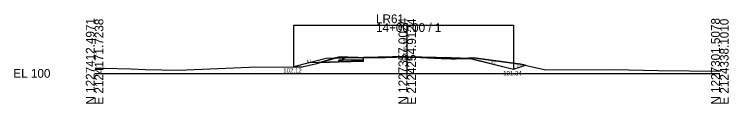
# Model space of a CAD drawing. Extents: x 2121193 to 2127979, y 1225108 to 1234639.
# Drawn here: x 2127750.9 to 2127979.4, y 1229107.5 to 1229136.1 of the extents above; entities that cross this region are included whole.
import ezdxf

# ---------------------------------------------------------------- set-up
doc = ezdxf.new("R2010")
doc.units = 0
for name, color, linetype in [('XS_CELL', 7, 'Continuous'), ('XS_M_DITCH', 7, 'Continuous'), ('XS_M_SHAPES_EARTHWORK', 7, 'Continuous'), ('XS_P_FINISHED_GRADE', 7, 'Continuous'), ('XS_P_FINISHED_GRADE_ELEV_TX', 7, 'Continuous'), ('XS_P_SUBGRADE_GRANULAR', 7, 'Continuous'), ('XS_P_SUBGRADE_LEVELING', 7, 'Continuous'), ('XS_P_SUBGRADE_PAVEMENT', 7, 'Continuous'), ('XS_P_TX_DCH', 7, 'Continuous'), ('XS_P_TX_FS_BS', 7, 'Continuous'), ('XS_X_GROUND', 7, 'Continuous'), ('XS_X_GROUND_TX', 7, 'Continuous')]:
    doc.layers.add(name, color=color, linetype=linetype)

msp = doc.modelspace()

# ---------------------------------------------------------------- linework, layer by layer
at = {"layer": 'XS_CELL'}
for p, q in [((2127876.61, 1229117.21), (2127876.61, 1229133.25)), ((2127776.61, 1229117.21), (2127876.61, 1229117.21)), ((2127876.61, 1229117.21), (2127976.61, 1229117.21))]:
    msp.add_line(p, q, dxfattribs=at)
at = {"layer": 'XS_M_DITCH'}
for p, q in [((2127840.32, 1229119.33), (2127840.32, 1229132.57)), ((2127840.32, 1229132.57), (2127910.61, 1229132.57)), ((2127910.61, 1229132.57), (2127910.61, 1229118.55))]:
    msp.add_line(p, q, dxfattribs=at)
at = {"layer": 'XS_M_SHAPES_EARTHWORK'}
for p, q in [((2127853.28, 1229122.03), (2127848.77, 1229120.69)), ((2127855.01, 1229122.55), (2127853.28, 1229122.03)), ((2127856.72, 1229122.17), (2127853.28, 1229122.03)), ((2127853.28, 1229122.03), (2127856.72, 1229122.17)), ((2127857.65, 1229122.41), (2127855.01, 1229122.55)), ((2127855.89, 1229121.45), (2127856.04, 1229121.7)), ((2127856.04, 1229121.7), (2127855.89, 1229121.45)), ((2127862.61, 1229121.58), (2127855.89, 1229121.45)), ((2127855.89, 1229121.45), (2127862.61, 1229121.58)), ((2127856.04, 1229121.7), (2127856.72, 1229122.17)), ((2127856.72, 1229122.17), (2127856.04, 1229121.7)), ((2127856.72, 1229122.17), (2127861, 1229122.26)), ((2127861, 1229122.26), (2127856.72, 1229122.17)), ((2127861, 1229122.26), (2127857.65, 1229122.41)), ((2127862.3, 1229122.2), (2127861, 1229122.26)), ((2127862.61, 1229122.2), (2127862.3, 1229122.2)), ((2127862.61, 1229121.08), (2127862.61, 1229121.58)), ((2127890.68, 1229122.16), (2127890.68, 1229121.83)), ((2127894.85, 1229122), (2127890.68, 1229122.16)), ((2127890.68, 1229121.83), (2127890.97, 1229121.82)), ((2127890.97, 1229121.82), (2127892.29, 1229121.87)), ((2127892.29, 1229121.87), (2127894.85, 1229122)), ((2127896.24, 1229122.06), (2127894.85, 1229122)), ((2127894.85, 1229122), (2127897.2, 1229121.9)), ((2127897.78, 1229122.14), (2127896.24, 1229122.06)), ((2127896.61, 1229122.05), (2127896.24, 1229122.06)), ((2127896.24, 1229122.06), (2127896.61, 1229122.05)), ((2127897.2, 1229121.9), (2127896.61, 1229122.05)), ((2127912.88, 1229120.2), (2127897.78, 1229122.14)), ((2127845.15, 1229120.54), (2127840.32, 1229119.33)), ((2127840.32, 1229119.33), (2127842.96, 1229119.35)), ((2127842.96, 1229119.35), (2127847.67, 1229120.35)), ((2127848.77, 1229120.69), (2127845.15, 1229120.54)), ((2127847.67, 1229120.35), (2127848.77, 1229120.69)), ((2127848.77, 1229120.69), (2127854.72, 1229120.92)), ((2127854.72, 1229121.42), (2127855.89, 1229121.45)), ((2127855.89, 1229121.45), (2127854.72, 1229121.42)), ((2127854.72, 1229120.92), (2127854.72, 1229121.42)), ((2127854.72, 1229121.42), (2127854.72, 1229120.92)), ((2127854.72, 1229120.92), (2127862.61, 1229121.08)), ((2127910.61, 1229118.55), (2127914.45, 1229119.83)), ((2127914.45, 1229119.83), (2127912.88, 1229120.2))]:
    msp.add_line(p, q, dxfattribs=at)
for points in [[(2127862.61, 1229121.58), (2127862.61, 1229122.16), (2127862.61, 1229122.2)], [(2127896.61, 1229122.05), (2127897.2, 1229121.9), (2127910.61, 1229118.55)]]:
    msp.add_lwpolyline(points, dxfattribs=at)
at = {"layer": 'XS_P_FINISHED_GRADE'}
for p, q in [((2127850.72, 1229121.93), (2127840.32, 1229119.33)), ((2127856.72, 1229122.17), (2127850.72, 1229121.93)), ((2127862.61, 1229122.29), (2127856.72, 1229122.17)), ((2127876.61, 1229122.57), (2127862.61, 1229122.29)), ((2127876.61, 1229122.57), (2127890.61, 1229122.29)), ((2127890.61, 1229122.29), (2127896.61, 1229122.05)), ((2127896.61, 1229122.05), (2127910.61, 1229118.55)), ((2127910.61, 1229118.55), (2127914.45, 1229119.83))]:
    msp.add_line(p, q, dxfattribs=at)
at = {"layer": 'XS_P_SUBGRADE_GRANULAR'}
for p, q in [((2127862.61, 1229121.08), (2127862.61, 1229121.58)), ((2127890.68, 1229122.16), (2127897.2, 1229121.9)), ((2127854.72, 1229120.92), (2127845.15, 1229120.54)), ((2127855.89, 1229121.45), (2127854.72, 1229121.42)), ((2127854.72, 1229120.92), (2127854.72, 1229121.42)), ((2127862.61, 1229121.08), (2127854.72, 1229120.92))]:
    msp.add_line(p, q, dxfattribs=at)
at = {"layer": 'XS_P_SUBGRADE_LEVELING'}
for p, q in [((2127887.46, 1229121.94), (2127876.79, 1229122.44)), ((2127890.68, 1229121.83), (2127887.46, 1229121.94))]:
    msp.add_line(p, q, dxfattribs=at)
at = {"layer": 'XS_P_SUBGRADE_PAVEMENT'}
for p, q in [((2127856.04, 1229121.7), (2127855.89, 1229121.45)), ((2127862.61, 1229121.58), (2127855.89, 1229121.45)), ((2127856.72, 1229122.17), (2127856.04, 1229121.7)), ((2127876.61, 1229122.44), (2127862.61, 1229122.16)), ((2127862.61, 1229121.58), (2127862.61, 1229122.16)), ((2127876.61, 1229122.44), (2127890.68, 1229122.16)), ((2127890.61, 1229122.29), (2127890.68, 1229122.16))]:
    msp.add_line(p, q, dxfattribs=at)
at = {"layer": 'XS_X_GROUND'}
for p, q in [((2127847.67, 1229120.35), (2127855.01, 1229122.55)), ((2127855.01, 1229122.55), (2127857.65, 1229122.41)), ((2127857.65, 1229122.41), (2127862.3, 1229122.2)), ((2127862.3, 1229122.2), (2127869.62, 1229122.31)), ((2127869.62, 1229122.31), (2127876.61, 1229122.45)), ((2127876.61, 1229122.45), (2127887.46, 1229121.94)), ((2127887.46, 1229121.94), (2127890.97, 1229121.82)), ((2127890.97, 1229121.82), (2127892.29, 1229121.87)), ((2127892.29, 1229121.87), (2127897.78, 1229122.14)), ((2127897.78, 1229122.14), (2127912.88, 1229120.2)), ((2127803.48, 1229118.24), (2127826.07, 1229119.21)), ((2127826.07, 1229119.21), (2127842.96, 1229119.35)), ((2127842.96, 1229119.35), (2127847.67, 1229120.35)), ((2127912.88, 1229120.2), (2127920.96, 1229118.29)), ((2127776.78, 1229118.83), (2127779.8, 1229118.87)), ((2127779.8, 1229118.87), (2127788.2, 1229118.7)), ((2127788.2, 1229118.7), (2127792.8, 1229118.43)), ((2127792.8, 1229118.43), (2127803.48, 1229118.24)), ((2127920.96, 1229118.29), (2127942.81, 1229118.43)), ((2127942.81, 1229118.43), (2127956.84, 1229118.09)), ((2127956.84, 1229118.09), (2127976.78, 1229117.9))]:
    msp.add_line(p, q, dxfattribs=at)

# ---------------------------------------------------------------- texts
at = {"layer": 'XS_CELL'}
for s, p in [('LR61', (2127866.61, 1229133.25)), ('14+00.00 / 1', (2127866.61, 1229130.45)), ('EL 100', (2127750.61, 1229115.81))]:
    msp.add_text(s, height=2.8, dxfattribs=at).set_placement(p)
for s, p in [('N 1227412.4971', (2127776.61, 1229107.21)), ('E 2124171.7238', (2127779.41, 1229107.21)), ('N 1227357.0024', (2127876.61, 1229107.21)), ('E 2124254.9124', (2127879.41, 1229107.21)), ('N 1227301.5078', (2127976.61, 1229107.21)), ('E 2124338.1010', (2127979.41, 1229107.21))]:
    msp.add_text(s, height=2.8, rotation=90, dxfattribs=at).set_placement(p)
at = {"layer": 'XS_P_FINISHED_GRADE_ELEV_TX'}
msp.add_text(' 105.36', height=1.25, rotation=90, dxfattribs=at).set_placement((2127876.61, 1229122.57))
at = {"layer": 'XS_P_TX_DCH'}
for s, p in [('102.12', (2127836.97, 1229117.44)), ('101.34', (2127907.31, 1229116.55))]:
    msp.add_text(s, height=1.4, dxfattribs=at).set_placement(p)
at = {"layer": 'XS_P_TX_FS_BS'}
for s, rotation, p in [('4:1', 14.0362, (2127844.54, 1229120.58)), ('4:1', 345.9638, (2127903.38, 1229120.61)), ('3:1', 18.4349, (2127911.72, 1229119.36))]:
    msp.add_text(s, height=0.8, rotation=rotation, dxfattribs=at).set_placement(p)
at = {"layer": 'XS_X_GROUND_TX'}
msp.add_text('105.24', height=1, dxfattribs=at).set_placement((2127874.22, 1229121.28))

doc.saveas('drawing.dxf')
